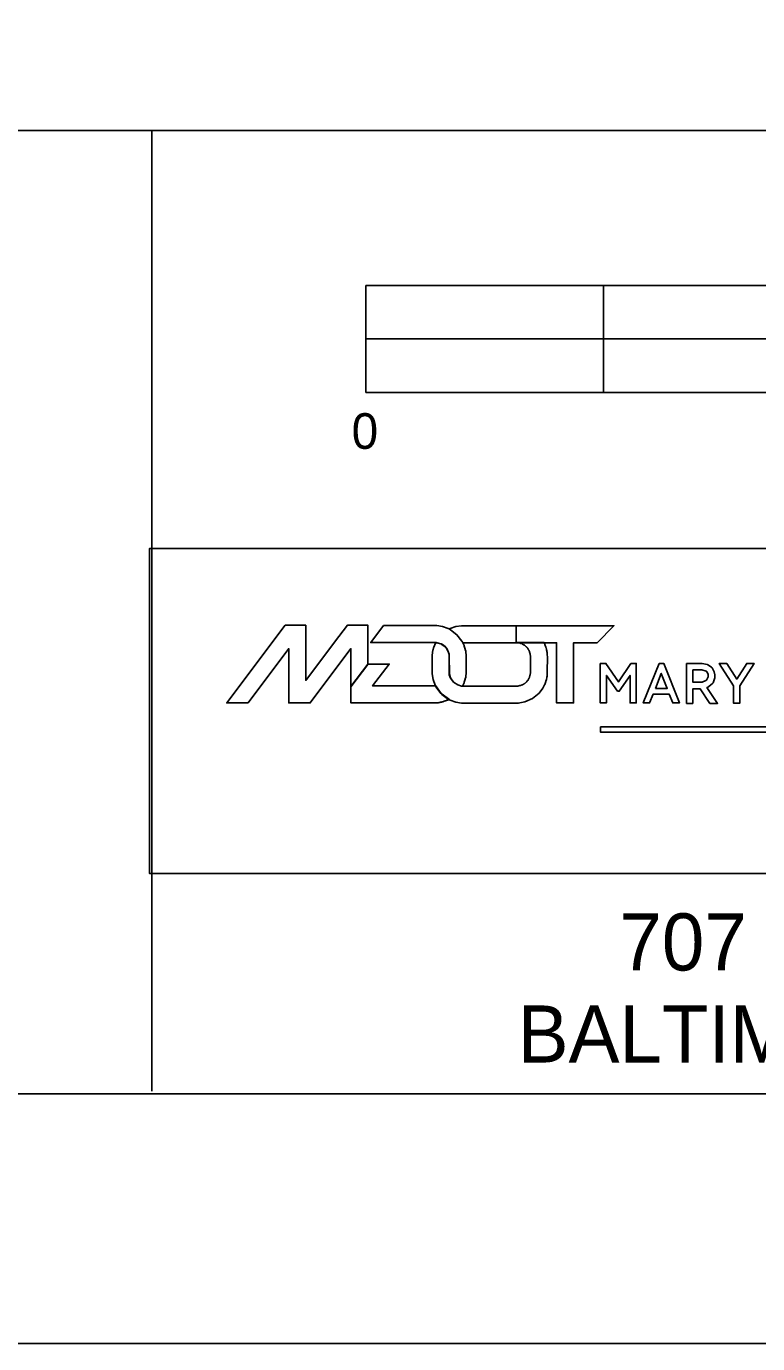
# Model space of a CAD drawing. Extents: x -1 to 9.2, y 0 to 14.8.
# Drawn here: x 2.774 to 3.799, y 0 to 1.846 of the extents above; entities that cross this region are included whole.
import ezdxf

# ---------------------------------------------------------------- set-up
doc = ezdxf.new("R2010")
doc.units = 0
for name, color, linetype in [('G-BORD-LINE', 7, 'Continuous'), ('G-BORD-SCAL', 7, 'Continuous'), ('G-MSHA-LOGO', 7, 'Continuous'), ('G-USER-LINE', 7, 'Continuous'), ('G-USER-PAGE', 7, 'Continuous')]:
    doc.layers.add(name, color=color, linetype=linetype)

msp = doc.modelspace()

# ---------------------------------------------------------------- linework, layer by layer
at = {"layer": 'G-BORD-LINE'}
for p, q in [((0.35, 1.7), (8.15, 1.7)), ((2.95, 0.354), (2.95, 1.7))]:
    msp.add_line(p, q, dxfattribs=at)
msp.add_lwpolyline([(0.35, 0.8607), (0.35, 0.35), (8.15, 0.35), (8.15, 10.65), (0.35, 10.65), (0.35, 0.8607)], dxfattribs=at)
at = {"layer": 'G-BORD-SCAL'}
for p, q in [((3.25, 1.333), (3.25, 1.483)), ((5.25, 1.483), (3.25, 1.483)), ((5.25, 1.483), (3.25, 1.483)), ((3.583, 1.333), (3.583, 1.483)), ((4.25, 1.408), (3.25, 1.408)), ((5.25, 1.333), (3.25, 1.333)), ((5.25, 1.333), (3.25, 1.333))]:
    msp.add_line(p, q, dxfattribs=at)
for points in [[(3.583, 1.483), (3.917, 1.483), (3.917, 1.408), (3.583, 1.408)], [(3.25, 1.333), (3.583, 1.333), (3.583, 1.408), (3.25, 1.408)]]:
    msp.add_lwpolyline(points, close=True, dxfattribs=at)
at = {"layer": 'G-MSHA-LOGO'}
for points in [[(3.2291, 0.9203), (3.2529, 0.952), (3.2529, 1.0068), (3.224, 1.0068), (3.206, 0.9829), (3.1658, 0.9294), (3.1658, 1.0068), (3.1369, 1.0068), (3.055, 0.898), (3.0849, 0.898), (3.142, 0.974), (3.142, 0.898), (3.172, 0.898), (3.2291, 0.974)], [(3.3477, 0.9824), (3.3484, 0.9824), (3.3551, 0.9806), (3.3557, 0.9803), (3.3564, 0.9799), (3.3597, 0.9775), (3.3626, 0.9746), (3.363, 0.974), (3.3636, 0.9732), (3.3655, 0.9691), (3.3666, 0.9647), (3.3667, 0.9637), (3.3667, 0.9637), (3.3667, 0.9636), (3.3667, 0.9636), (3.3667, 0.9634), (3.3667, 0.9628), (3.3667, 0.9627), (3.3667, 0.942), (3.3667, 0.9418), (3.3667, 0.9413), (3.3667, 0.9411), (3.3667, 0.9411), (3.3667, 0.941), (3.3667, 0.941), (3.3667, 0.9405), (3.3665, 0.9395), (3.3665, 0.9392), (3.3668, 0.9375), (3.3687, 0.9325), (3.3728, 0.9271), (3.3787, 0.9232), (3.3841, 0.9215), (3.3853, 0.9214), (3.3855, 0.9218), (3.3857, 0.922), (3.3857, 0.922), (3.3858, 0.9224), (3.3876, 0.9262), (3.3878, 0.9266), (3.3879, 0.9271), (3.3892, 0.9312), (3.3893, 0.9316), (3.3893, 0.9319), (3.3898, 0.934), (3.3899, 0.9342), (3.39, 0.9348), (3.3906, 0.9403), (3.3906, 0.9422), (3.3906, 0.9624), (3.3906, 0.9644), (3.39, 0.9697), (3.3899, 0.9704), (3.3898, 0.9706), (3.3893, 0.9727), (3.3893, 0.9729), (3.3892, 0.9733), (3.3879, 0.9775), (3.3878, 0.9779), (3.3876, 0.9783), (3.3858, 0.9822), (3.3857, 0.9826), (3.3846, 0.9846), (3.3776, 0.9935), (3.3687, 1.0005), (3.3667, 1.0016), (3.3652, 1.0023), (3.3571, 1.0052), (3.3492, 1.0064), (3.3466, 1.0064), (3.2747, 1.0064), (3.2568, 0.9826), (3.3466, 0.9826), (3.3467, 0.9825), (3.3474, 0.9824)], [(3.3858, 0.9823), (3.3862, 0.9823), (3.3864, 0.9823), (3.4601, 0.9823), (3.4602, 0.9823), (3.4605, 0.9823), (3.4605, 0.9823), (3.4607, 0.9826), (3.4607, 1.0062), (3.4607, 1.0062), (3.4602, 1.0062), (3.4601, 1.0062), (3.3864, 1.0062), (3.3838, 1.0062), (3.3759, 1.0049), (3.3679, 1.0021), (3.3667, 1.0016), (3.3687, 1.0005), (3.3776, 0.9935), (3.3846, 0.9846), (3.3857, 0.9826)], [(3.4607, 1.0062), (3.4607, 0.9824), (3.5172, 0.9824), (3.5172, 0.898), (3.5409, 0.898), (3.5409, 0.9824), (3.5739, 0.9824), (3.5975, 1.0061), (3.5975, 1.0062)], [(3.3671, 0.9028), (3.367, 0.9028), (3.3668, 0.903), (3.3668, 0.903), (3.3658, 0.9035), (3.3568, 0.9102), (3.356, 0.911), (3.3552, 0.9118), (3.3487, 0.9207), (3.3481, 0.9217), (3.348, 0.9217), (3.3478, 0.9217), (3.3477, 0.9217), (3.3474, 0.9217), (3.3468, 0.9217), (3.3466, 0.9217), (3.2594, 0.9217), (3.2826, 0.9523), (3.2527, 0.9523), (3.2289, 0.9208), (3.2289, 0.8979), (3.3465, 0.8979), (3.3471, 0.8979), (3.349, 0.898), (3.3492, 0.898), (3.3498, 0.898), (3.3515, 0.8983), (3.3517, 0.8983), (3.3519, 0.8983), (3.3524, 0.8985), (3.3525, 0.8985), (3.3526, 0.8985), (3.354, 0.8987), (3.3542, 0.8988), (3.3544, 0.8988), (3.3549, 0.8989), (3.3551, 0.8989), (3.3552, 0.899), (3.3564, 0.8992), (3.3566, 0.8992), (3.3566, 0.8993), (3.3574, 0.8995), (3.3575, 0.8995), (3.3576, 0.8996), (3.3587, 0.8999), (3.3588, 0.9), (3.3589, 0.9), (3.3596, 0.9002), (3.3597, 0.9003), (3.3598, 0.9003), (3.361, 0.9007), (3.3611, 0.9007), (3.3612, 0.9008), (3.3619, 0.901), (3.362, 0.901), (3.3621, 0.9011), (3.3634, 0.9016), (3.3635, 0.9016), (3.3636, 0.9017), (3.3642, 0.9019), (3.3642, 0.9019), (3.3644, 0.902), (3.3662, 0.9029), (3.3664, 0.903), (3.3665, 0.9029), (3.3669, 0.9028)], [(3.5784, 0.9534), (3.5862, 0.9534), (3.604, 0.9275), (3.6213, 0.9534), (3.6288, 0.9534), (3.6288, 0.8979), (3.6201, 0.8979), (3.6201, 0.9364), (3.6049, 0.9143), (3.6026, 0.9143), (3.587, 0.9364), (3.587, 0.8979), (3.5784, 0.8979)], [(3.6607, 0.9534), (3.6674, 0.9534), (3.6892, 0.8979), (3.68, 0.8979), (3.6751, 0.9102), (3.6524, 0.9102), (3.6475, 0.8979), (3.6386, 0.8979)], [(3.6993, 0.8976), (3.6993, 0.9531), (3.7189, 0.9531), (3.7213, 0.9531), (3.728, 0.9519), (3.7287, 0.9517), (3.7293, 0.9515), (3.7344, 0.9481), (3.7347, 0.9477), (3.7351, 0.9472), (3.7377, 0.9427), (3.7379, 0.9422), (3.738, 0.9417), (3.7388, 0.9371), (3.7388, 0.9356), (3.7388, 0.9331), (3.7364, 0.9262), (3.7359, 0.9255), (3.7354, 0.9248), (3.7287, 0.9197), (3.7278, 0.9195), (3.7428, 0.8973), (3.7321, 0.8973), (3.7186, 0.9177), (3.7079, 0.9177), (3.7079, 0.8973), (3.6993, 0.8973)], [(3.7079, 0.9442), (3.7079, 0.9272), (3.7192, 0.9272), (3.7211, 0.9272), (3.7264, 0.9292), (3.7269, 0.9295), (3.7274, 0.9299), (3.7298, 0.9346), (3.7298, 0.9361), (3.7298, 0.9377), (3.7277, 0.9418), (3.7272, 0.9422), (3.7268, 0.9425), (3.7209, 0.9442), (3.7189, 0.9442)], [(3.7739, 0.9217), (3.7739, 0.8976), (3.7652, 0.8976), (3.7652, 0.9217), (3.7451, 0.9534), (3.7557, 0.9534), (3.7696, 0.9313), (3.7837, 0.9534), (3.794, 0.9534)], [(3.6558, 0.9183), (3.6722, 0.9183), (3.6639, 0.9393)], [(3.5786, 0.8643), (5.4382, 0.8643), (5.4382, 0.8571), (3.5786, 0.8571)]]:
    msp.add_lwpolyline(points, close=True, dxfattribs=at)
for points in [[(3.3667, 0.9511), (3.3667, 0.9624), (3.3667, 0.9627), (3.3667, 0.9634), (3.3667, 0.9636), (3.3667, 0.964), (3.3668, 0.965), (3.3668, 0.9654), (3.3667, 0.9662), (3.3638, 0.9735), (3.3633, 0.9741), (3.3629, 0.9748), (3.36, 0.9778), (3.3566, 0.9802), (3.3558, 0.9806), (3.3552, 0.9809), (3.3485, 0.9827), (3.3478, 0.9827), (3.3478, 0.9826), (3.3477, 0.9824), (3.3474, 0.9818), (3.345, 0.9759), (3.3448, 0.9753), (3.3447, 0.9751), (3.3441, 0.973), (3.3441, 0.9728), (3.3439, 0.9719), (3.3429, 0.9648), (3.3429, 0.9624), (3.3429, 0.9511), (3.3429, 0.9499)], [(3.5043, 0.9624), (3.5043, 0.963), (3.5041, 0.9647), (3.5041, 0.9649), (3.5041, 0.9651), (3.5041, 0.9657), (3.5041, 0.9661), (3.504, 0.9672), (3.504, 0.9675), (3.504, 0.9676), (3.504, 0.9679), (3.504, 0.9679), (3.504, 0.968), (3.504, 0.9682), (3.504, 0.9682), (3.5039, 0.9684), (3.5037, 0.9699), (3.5036, 0.9701), (3.5036, 0.9702), (3.5035, 0.9705), (3.5035, 0.9707), (3.5035, 0.9708), (3.5031, 0.9725), (3.5031, 0.9726), (3.5031, 0.9728), (3.5031, 0.9729), (3.503, 0.9731), (3.5024, 0.9754), (3.5023, 0.9756), (3.5022, 0.976), (3.5008, 0.9798), (3.5006, 0.9801), (3.5006, 0.9803), (3.4997, 0.9822), (3.4996, 0.9824), (3.4996, 0.9825), (3.4994, 0.9827), (3.4613, 0.9827), (3.4612, 0.9824), (3.4616, 0.9824), (3.4618, 0.9824), (3.4619, 0.9824), (3.4624, 0.9823), (3.4625, 0.9823), (3.4628, 0.9822), (3.4659, 0.9816), (3.4661, 0.9815), (3.4664, 0.9814), (3.4689, 0.9806), (3.4691, 0.9805), (3.4693, 0.9804), (3.4706, 0.9796), (3.4708, 0.9796), (3.4709, 0.9796), (3.4709, 0.9796), (3.4711, 0.9795), (3.4723, 0.9787), (3.4725, 0.9786), (3.4726, 0.9785), (3.4726, 0.9785), (3.4727, 0.9784), (3.4738, 0.9776), (3.474, 0.9774), (3.4741, 0.9773), (3.4742, 0.9772), (3.4751, 0.9763), (3.4752, 0.9762), (3.4753, 0.9761), (3.4753, 0.9761), (3.4755, 0.9759), (3.4755, 0.9759), (3.4762, 0.9751), (3.4762, 0.975), (3.4764, 0.9749), (3.4764, 0.9748), (3.4766, 0.9745), (3.4767, 0.9744), (3.4767, 0.9744), (3.4774, 0.9734), (3.4774, 0.9734), (3.4775, 0.9733), (3.4777, 0.9728), (3.4777, 0.9728), (3.4778, 0.9726), (3.4779, 0.9726), (3.4779, 0.9725), (3.4783, 0.9718), (3.4783, 0.9717), (3.4784, 0.9716), (3.4786, 0.971), (3.4786, 0.971), (3.4787, 0.9709), (3.479, 0.97), (3.4791, 0.9699), (3.4791, 0.9699), (3.4792, 0.9693), (3.4792, 0.9692), (3.4793, 0.969), (3.4794, 0.969), (3.4794, 0.9689), (3.4797, 0.9683), (3.4797, 0.9681), (3.4797, 0.968), (3.4799, 0.9671), (3.48, 0.967), (3.48, 0.9668), (3.4801, 0.9663), (3.4801, 0.9661), (3.4802, 0.966), (3.4803, 0.9652), (3.4803, 0.9649), (3.4803, 0.9647), (3.4804, 0.9643), (3.4804, 0.9642), (3.4804, 0.9637), (3.4806, 0.9626), (3.4806, 0.9622), (3.4806, 0.9416), (3.4806, 0.9411), (3.4805, 0.9398), (3.4804, 0.9396), (3.4804, 0.9394), (3.4803, 0.9389), (3.4803, 0.9389), (3.4803, 0.9386), (3.4801, 0.9379), (3.4801, 0.9377), (3.4801, 0.9374), (3.48, 0.9369), (3.48, 0.9368), (3.4799, 0.9367), (3.4797, 0.9358), (3.4797, 0.9357), (3.4797, 0.9356), (3.4794, 0.9349), (3.4794, 0.9348), (3.4794, 0.9347), (3.4793, 0.9345), (3.4792, 0.9345), (3.4791, 0.934), (3.4791, 0.9339), (3.479, 0.9338), (3.4787, 0.933), (3.4786, 0.9328), (3.4786, 0.9328), (3.4784, 0.9322), (3.4783, 0.9321), (3.4783, 0.932), (3.4779, 0.9312), (3.4779, 0.9312), (3.4778, 0.931), (3.4777, 0.931), (3.4777, 0.931), (3.4775, 0.9305), (3.4774, 0.9304), (3.4774, 0.9303), (3.4767, 0.9294), (3.4767, 0.9294), (3.4766, 0.9293), (3.4764, 0.929), (3.4764, 0.9289), (3.4762, 0.9288), (3.4761, 0.9287), (3.4755, 0.9279), (3.4755, 0.9279), (3.4753, 0.9277), (3.4752, 0.9276), (3.4752, 0.9276), (3.4751, 0.9275), (3.4742, 0.9266), (3.4741, 0.9265), (3.474, 0.9264), (3.4738, 0.9263), (3.4727, 0.9254), (3.4726, 0.9253), (3.4725, 0.9252), (3.4725, 0.9251), (3.4723, 0.9251), (3.4711, 0.9243), (3.4709, 0.9242), (3.4708, 0.9242), (3.4708, 0.9242), (3.4707, 0.9242), (3.4693, 0.9234), (3.4691, 0.9233), (3.4689, 0.9232), (3.4664, 0.9224), (3.4661, 0.9223), (3.4658, 0.9222), (3.4628, 0.9216), (3.4625, 0.9215), (3.4623, 0.9215), (3.4618, 0.9214), (3.4618, 0.9214), (3.4615, 0.9214), (3.4609, 0.9214), (3.4607, 0.9214), (3.387, 0.9214), (3.3867, 0.9214), (3.3861, 0.9214), (3.386, 0.9214), (3.3841, 0.9215), (3.3787, 0.9232), (3.3728, 0.9272), (3.3687, 0.9331), (3.3671, 0.9384), (3.367, 0.9402), (3.367, 0.9405), (3.367, 0.9412), (3.367, 0.9414), (3.367, 0.9511), (3.3667, 0.9511)], [(3.3429, 0.9499), (3.3429, 0.9414), (3.3429, 0.9388), (3.3441, 0.931), (3.3469, 0.9229), (3.3477, 0.9214), (3.3482, 0.9204), (3.3549, 0.9112), (3.3557, 0.9104), (3.3564, 0.9096), (3.3656, 0.9029), (3.3667, 0.9024), (3.3682, 0.9016), (3.3762, 0.8988), (3.3841, 0.8976), (3.3867, 0.8976), (3.4604, 0.8976), (3.4635, 0.8976), (3.4726, 0.8993), (3.4835, 0.9042), (3.4926, 0.9117), (3.4981, 0.9188), (3.4994, 0.9214), (3.4995, 0.9216), (3.5004, 0.9234), (3.5005, 0.9236), (3.5006, 0.924), (3.502, 0.9278), (3.5021, 0.9282), (3.5022, 0.9284), (3.5029, 0.9307), (3.5029, 0.9309), (3.5029, 0.931), (3.5029, 0.9312), (3.5029, 0.9313), (3.5033, 0.933), (3.5033, 0.9331), (3.5033, 0.9333), (3.5035, 0.9336), (3.5035, 0.9337), (3.5035, 0.9339), (3.5038, 0.9354), (3.5038, 0.9355), (3.5038, 0.9356), (3.5038, 0.9358), (3.5038, 0.9358), (3.5038, 0.936), (3.5038, 0.9362), (3.5038, 0.9363), (3.5038, 0.9368), (3.504, 0.9378), (3.504, 0.9381), (3.504, 0.9387), (3.504, 0.9389), (3.504, 0.9395), (3.5041, 0.9409), (3.5041, 0.9414), (3.5043, 0.9624)]]:
    msp.add_lwpolyline(points, dxfattribs=at)
at = {"layer": 'G-USER-LINE'}
msp.add_lwpolyline([(5.5468, 0.6588), (2.9468, 0.6588), (2.9468, 1.1144), (5.5468, 1.1144)], close=True, dxfattribs=at)
at = {"layer": 'G-USER-PAGE'}
msp.add_lwpolyline([(0, 11), (8.5, 11), (8.5, 0), (0, 0)], close=True, dxfattribs=at)

# ---------------------------------------------------------------- texts
at = {"layer": 'G-BORD-LINE'}
for s, p in [('707 NORTH CALVERT ST.', (3.6052, 0.523)), ('BALTIMORE, MARYLAND 21202', (3.4626, 0.394))]:
    msp.add_text(s, height=0.079998, dxfattribs=at).set_placement(p)
at = {"layer": 'G-BORD-SCAL'}
msp.add_text('0', height=0.05, dxfattribs=at).set_placement((3.23, 1.254))

doc.saveas('drawing.dxf')
